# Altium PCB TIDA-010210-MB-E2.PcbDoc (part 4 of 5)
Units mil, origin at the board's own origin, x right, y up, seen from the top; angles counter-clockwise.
Board outline 11811.02 x 8661.42 mil, 4 copper layers (Top Layer, Gnd Layer, Pwr Layer, Bottom Layer), stack 94.4 mil thick; 473 components, 257 nets, 1291 pads, 289 vias.
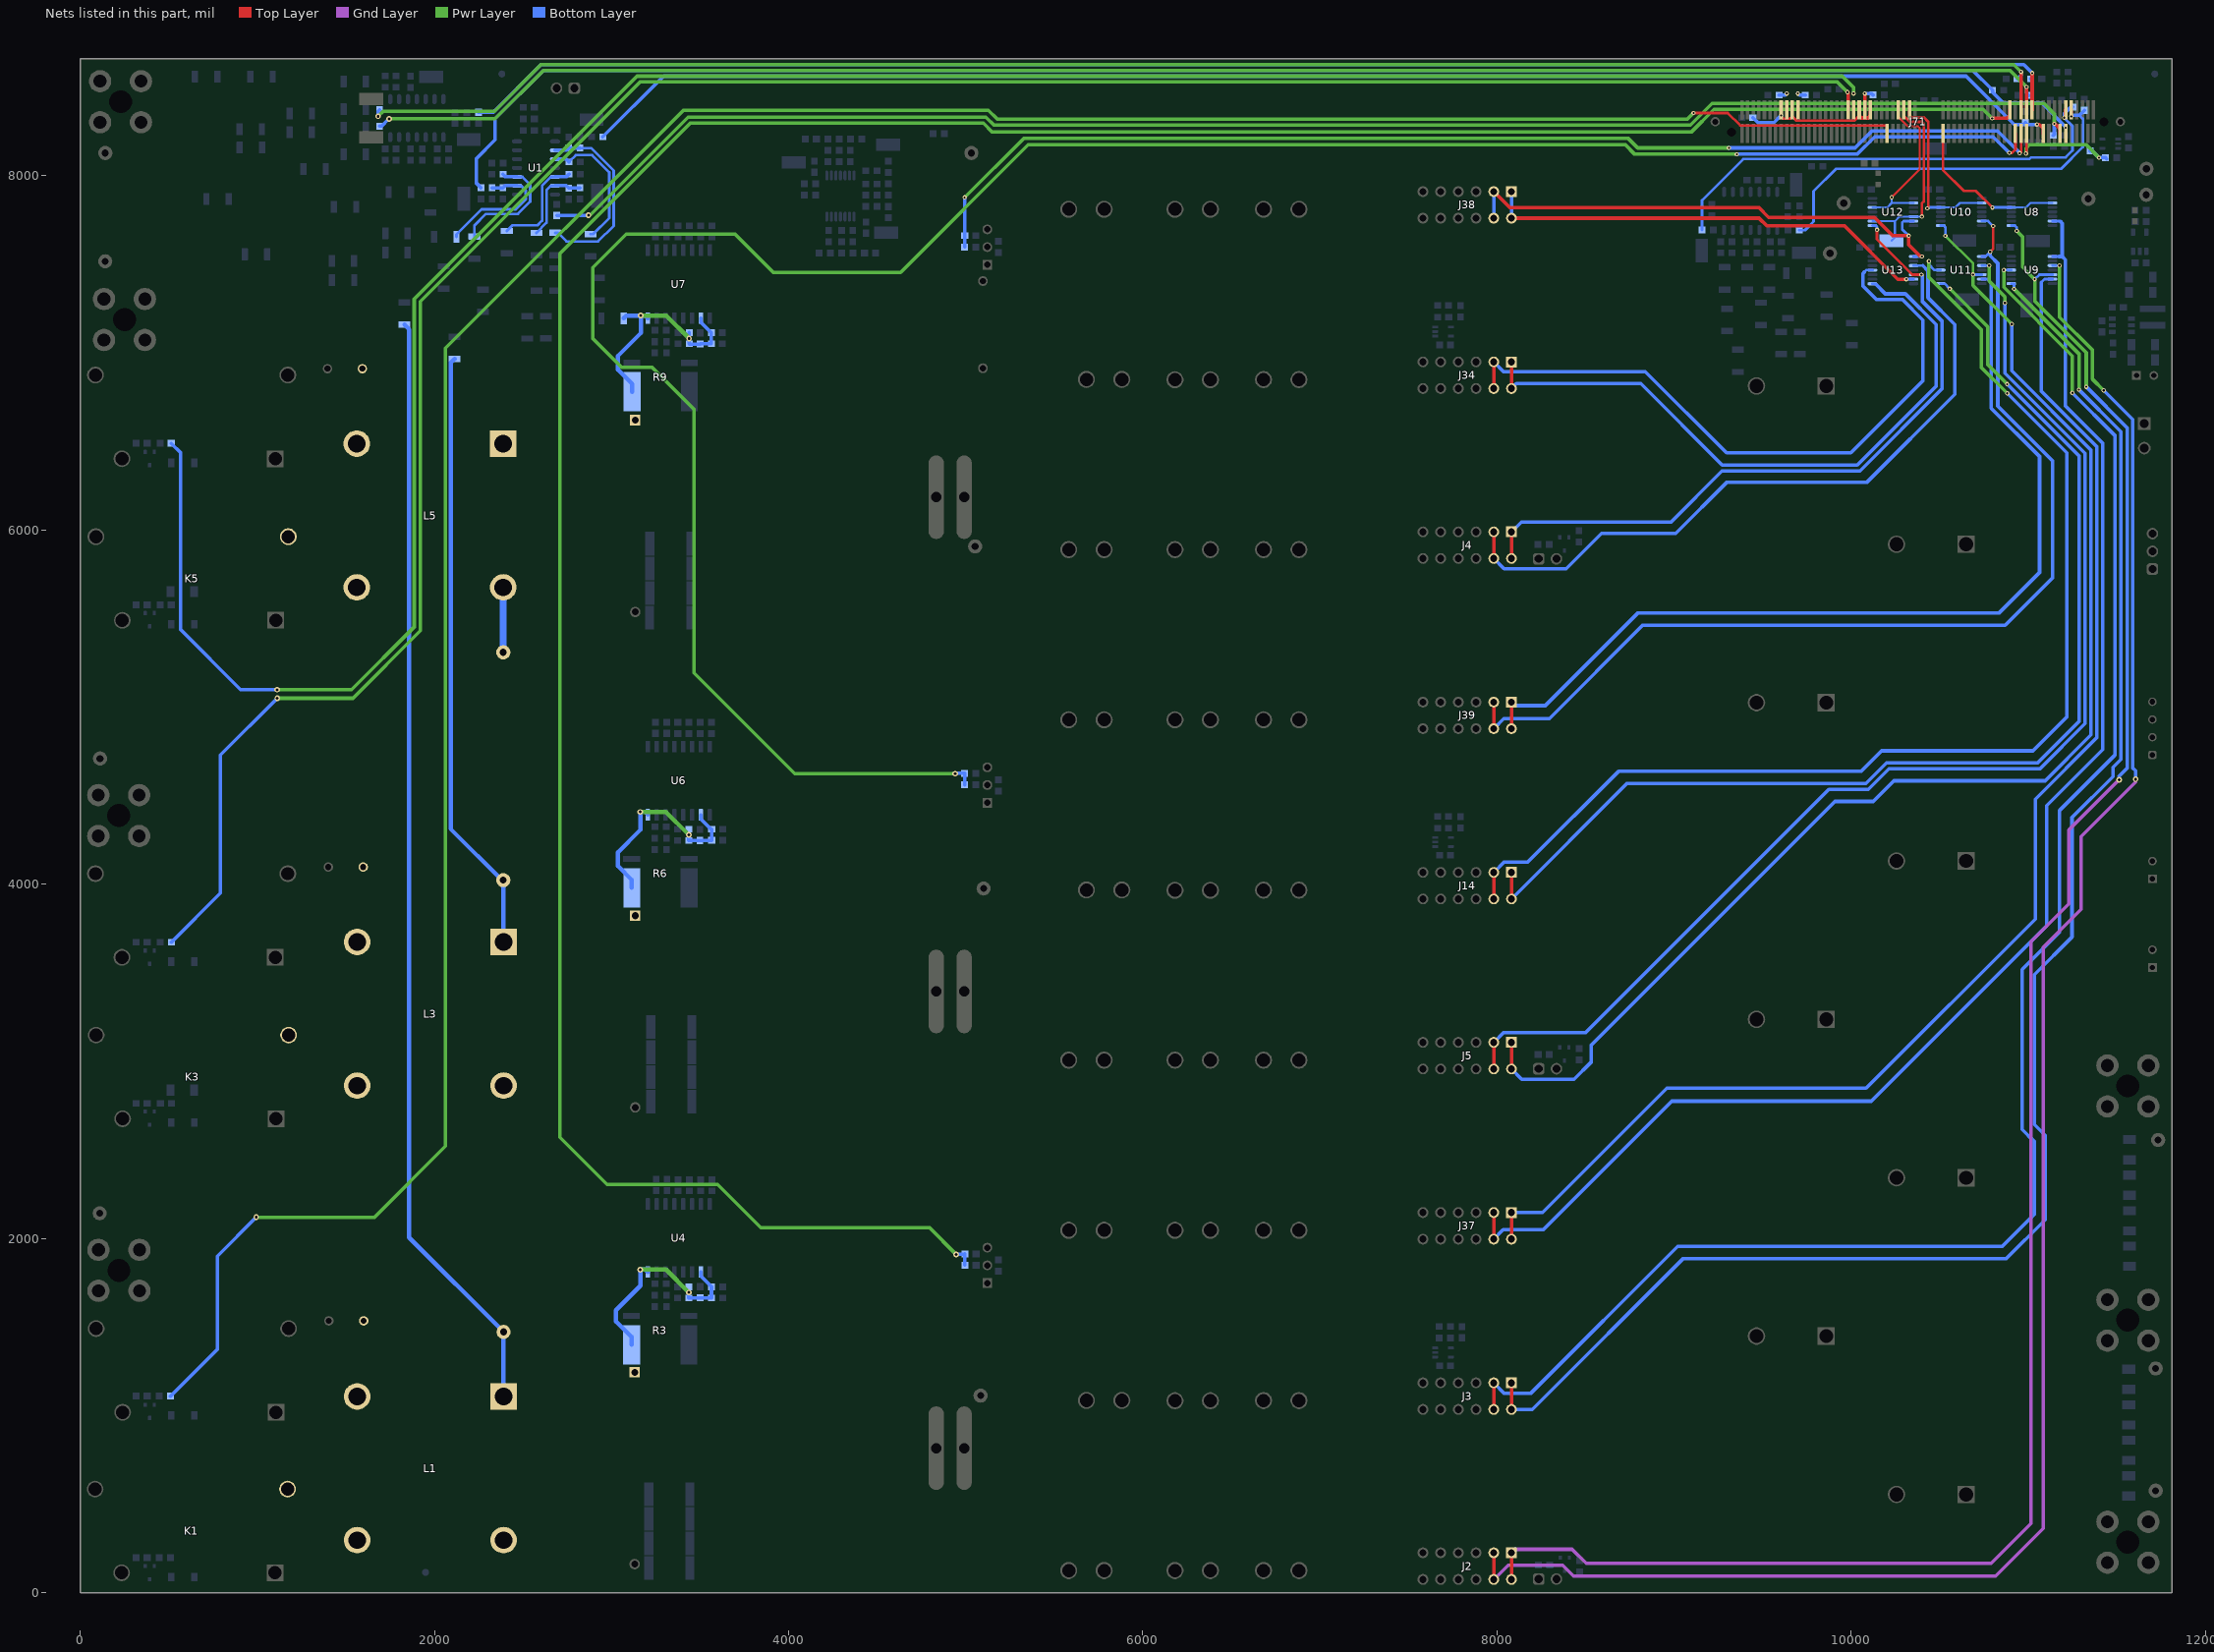
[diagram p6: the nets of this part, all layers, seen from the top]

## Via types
v1: diameter 24, hole 12, Top Layer to Bottom Layer, tented both sides, 169 vias
v2: diameter 32, hole 16, Top Layer to Bottom Layer, tented both sides, 102 vias
v3: diameter 50, hole 28, Top Layer to Bottom Layer, tented both sides, 18 vias

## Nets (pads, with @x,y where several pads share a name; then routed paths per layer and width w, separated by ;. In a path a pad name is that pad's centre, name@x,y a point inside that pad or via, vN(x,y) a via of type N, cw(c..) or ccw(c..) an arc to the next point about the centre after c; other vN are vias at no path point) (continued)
PWM+_C: J71.61 TP34.1 U12.5 U12.9 | length 1103.5
  Top Layer w15: J71.61@10296.51,8371.93 10296.51,8336.44 10329.71,8303.23 10399.82,8303.23 10409,8294.05 10409,7854.61 10398,7843.61 v1(10398,7769.19)
  Bottom Layer w12: U12.9@10119.04,7743.6 10119.04,7742.64 10245.4,7742.64 ; TP34.1@10227,7632.66 10245.4,7651.07 10245.4,7742.64 ; v1(10398,7769.19) U12.5@10351.33,7769.19 10271.96,7769.19 10245.4,7742.64
PWM-_A: J71.56 U8.2 U8.12 | length 923.3
  Top Layer w15: J71.56@10516.98,8238.07 10516.98,8031.52 10634.32,7914.18 10702.64,7914.18 v1(10796.45,7820.37)
  Bottom Layer w12: U8.12@10903.21,7820.77 10986.58,7820.77 11012.17,7846.36 U8.2@11135.49,7846.36
  Bottom Layer w15: v1(10796.45,7820.37) 10796.84,7820.77 U8.12@10903.21,7820.77
PWM-_B: J71.59 U10.2 U10.12 | length 963.4
  Top Layer w15: J71.59@10328,8371.93 10328,8342.11 10341.11,8329 10410.32,8329 10434,8305.32 10434,7820.37 v1(10429,7815.37)
  Bottom Layer w12: U10.12@10504.18,7820.77 10587.55,7820.77 10613.14,7846.36 U10.2@10736.46,7846.36
  Bottom Layer w15: v1(10429,7815.37) 10434.39,7820.77 U10.12@10504.18,7820.77
PWM-_C: J71.63 U12.2 U12.12 | length 919.2
  Top Layer w12: v1(10228,7877.78) 10386,8035.78 10386,8270 10376.86,8279.14 10317.5,8279.14 10265.01,8331.63 J71.63@10265.01,8371.93
  Bottom Layer w12: U12.12@10119.04,7820.37 10202.41,7820.37 10228,7845.97 ; v1(10228,7877.78) 10228,7845.97 ; U12.2@10351.33,7845.97 10228,7845.97
PWM_S1A: J2.1 U8.8 U9.5 | length 11142.9
  Top Layer w20: J2.1@8081.32,75.11 J2.1@8081.32,225.11
  Gnd Layer w20: J2.1@8081.32,225.11 8101.32,245.11 8423.89,245.11 8503,166 10788.68,166 11014,391.32 11014,3674.51 11228,3888.51 11228,4306 v2(11512,4590)
  Pwr Layer w20: v1(10933.49,7687.54) 10966.35,7654.68 10966.35,7484.18 v1(11035.35,7415.18) 11035.35,7292.65 11326.25,7001.75 v1(11326.25,6808.07)
  Bottom Layer w15: U8.8@10903.21,7718.41 10923.59,7718.41 10933.49,7708.51 v1(10933.49,7687.54) ; v1(11035.35,7415.18) 11061.68,7441.51 U9.5@11135.49,7441.51
  Bottom Layer w20: v1(11326.25,6808.07) 11557,6577.32 11557,4655 11512,4610
PWM_S1B: J5.1 U10.8 U11.5 | length 7593.4
  Top Layer w20: J5.1@8081.32,2957 J5.1@8081.32,3107
  Pwr Layer w15: v1(10531,7660.56) 10686.99,7504.57 v1(10686.99,7441.74)
  Pwr Layer w20: v1(10686.99,7441.74) 10686.99,7380.46 10905.46,7162 v1(10906,7162)
  Bottom Layer w15: U10.8@10504.18,7718.41 10520.59,7718.41 10531.43,7707.57 10531.43,7660.99 v1(10531,7660.56) ; v1(10686.99,7441.74) 10687.22,7441.51 U11.5@10736.46,7441.51
  Bottom Layer w20: J5.1@8081.32,2957 8139.32,2899 8435,2899 8530.5,2994.5 8530.5,3089.5 9908,4467 10123,4467 10240,4584 11094,4584 11353,4843 11353,6451 10906,6898 v1(10906,7162)
PWM_S1C: J4.1 U12.8 U13.5 | length 4085.3
  Top Layer w15: v1(10145,7694.39) 10145,7641.04 10345.08,7440.96 v1(10395.82,7440.96)
  Top Layer w20: J4.1@8081.32,5838.89 J4.1@8081.32,5988.89
  Bottom Layer w15: U12.8@10119.04,7718.01 10136.99,7718.01 10145,7710 v1(10145,7694.39) ; U13.5@10350.97,7440.76 U13.5@10351.33,7441.12 v1@10395.67,7441.12
  Bottom Layer w20: J4.1@8081.32,5988.89 8137.32,6044.89 8981.89,6044.89 9270,6333 10048,6333 10513.03,6798.03 10513.03,7178 10400.19,7290.84 10400.19,7436.6 v1(10395.82,7440.96) v1@10395.67,7441.12
PWM_S2A: J2.2 U9.3 | length 10986.7
  Top Layer w20: J2.2@7981.32,75.11 J2.2@7981.32,225.11
  Gnd Layer w20: J2.2@7981.32,75.11 8061.94,155.73 8370.27,155.73 8432,94 10814.5,94 11083,362.5 11083,3645 11297,3859 11297,4269 11605,4577 v2(11605,4593)
  Pwr Layer w20: v1(11175.14,7492.69) 11175.14,7201.56 11362,7014.7 11362,6850.5 v1(11424.5,6788)
  Bottom Layer w15: U9.3@11135.98,7493.18 U9.3@11135.49,7492.69 v1(11175.14,7492.69)
  Bottom Layer w20: v1(11424.5,6788) 11589,6623.5 11589,4656 11605,4640 v2(11605,4593)
PWM_S2B: J5.2 U11.3 | length 7086.1
  Top Layer w20: J5.2@7981.32,2957 J5.2@7981.32,3107
  Pwr Layer w20: v1(10778,7492.56) 10778,7404.78 10867,7315.78 v1(10867,7281.46)
  Bottom Layer w15: U11.3@10736.46,7492.69 10777.87,7492.69 v1(10778,7492.56)
  Bottom Layer w20: J5.2@7981.32,3107 8037.32,3163 8501,3163 9873,4535 10096,4535 10213,4652 11065.35,4652 11320,4906.65 11320,6432.37 10867,6885.37 v1(10867,7281.46)
PWM_S2C: J4.2 U13.3 | length 4039.2
  Top Layer w20: J4.2@7981.32,5838.89 J4.2@7981.32,5988.89
  Bottom Layer w15: U13.3@10351.33,7492.3 10403.19,7492.3
  Bottom Layer w20: J4.2@7981.32,5838.89 8039.32,5780.89 8389.89,5780.89 8589,5980 9008,5980 9298,6270 10089,6270 10585,6766 10585,7159 10432.82,7311.18 10432.82,7462.26 10403.19,7491.9 10403.19,7492.3
PWM_S3A: J37.1 U9.6 | length 7732.3
  Top Layer w20: J37.1@8081.32,1996.37 J37.1@8081.32,2146.37
  Bottom Layer w15: 11071.35,7396.6 11090.66,7415.92 U9.6@11135.49,7415.92
  Bottom Layer w20: J37.1@8081.32,2146.37 8256.97,2146.37 8958.6,2848 10083,2848 11038.3,3803.3 11038.3,4480.3 11385,4827 11385,6471.05 11071.35,6784.7 11071.35,7396.6
PWM_S3B: J39.1 U11.6 | length 5260.1
  Top Layer w20: J39.1@8081.32,4878.26 J39.1@8081.32,5028.26
  Bottom Layer w15: U11.6@10736.46,7415.92 10766.87,7415.92 10789.82,7392.96
  Bottom Layer w20: J39.1@8081.32,5028.26 8101.58,5008 8272,5008 8796,5532 10835,5532 11062.48,5759.48 11062.48,6414.36 10789.86,6686.98 10789.86,7392.92 10789.82,7392.96
PWM_S3C: J38.1 U13.6 | length 2562.8
  Top Layer w20: J38.1@8081.32,7760.15 9479.02,7760.15 9521.15,7718.01 9959.93,7718.01 10262.41,7415.52 v1(10310.17,7415.52)
  Bottom Layer w15: v1(10310.17,7415.52) U13.6@10351.33,7415.52
  Bottom Layer w20: J38.1@8081.32,7760.15 J38.1@8081.32,7910.15
PWM_S4A: J37.2 U8.6 U9.1 | length 8311.7
  Top Layer w20: J37.2@7981.32,1996.37 J37.2@7981.32,2146.37
  Bottom Layer w15: U9.1@11135.49,7545.01 11136.84,7543.66 11173,7543.66 ; U8.6@11135.49,7744 11136.49,7743 11178.9,7743
  Bottom Layer w20: J37.2@7981.32,1996.37 8033.95,2049 8261,2049 8987,2775 10113,2775 11103,3765 11103,4444 11419,4760 11419,6490 11208.72,6700.28 11208.72,7525.09 11190.15,7543.66 ; 11173,7543.66 11190.15,7543.66 ; 11178.9,7743 11190.15,7731.75 11190.15,7543.66
PWM_S4B: J39.2 U10.6 U11.1 | length 5930.3
  Top Layer w15: v1(10784.23,7570.36) 10800.24,7586.38 v1(10800.24,7715.54)
  Top Layer w20: J39.2@7981.32,4878.26 J39.2@7981.32,5028.26
  Bottom Layer w15: U11.1@10736.46,7543.87 10757.74,7543.87 v1(10784.23,7570.36) ; U10.6@10736.46,7744 10771.79,7744 v1(10800.24,7715.54)
  Bottom Layer w20: J39.2@7981.32,4878.26 8038.06,4935 8295,4935 8821,5461 10868,5461 11136,5729 11136,6390 10827,6699 10827,7504.98 10784.23,7547.76 v1(10784.23,7570.36)
PWM_S4C: J38.2 U12.6 U13.1 | length 2956.4
  Top Layer w15: v1(10398.39,7543.48) v1@10400.19,7545.27
  Top Layer w20: J38.2@7981.32,7910.15 8072.47,7819 9478.48,7819 9533.48,7764 10130.19,7764 10233.4,7660.78 v1(10324.19,7660.78) 10324.19,7610.08 10389,7545.27 v1@10400.19,7545.27
  Bottom Layer w15: v1(10324.19,7660.78) 10287.19,7697.78 10287.19,7734.78 10296,7743.6 U12.6@10351.33,7743.6 ; U13.1@10351.33,7543.48 v1(10398.39,7543.48)
  Bottom Layer w20: J38.2@7981.32,7760.15 J38.2@7981.32,7910.15
PWM_S5A: J3.1 U9.8 | length 9383.5
  Top Layer w20: J3.1@8081.32,1034.74 J3.1@8081.32,1184.74
  Pwr Layer w20: v1(10918.38,7361.06) 11285.04,6994.39 v1(11285.04,6791.54)
  Bottom Layer w15: U9.8@10903.21,7390.33 10918.38,7390.33 v1(10918.38,7361.06)
  Bottom Layer w20: J3.1@8081.32,1034.74 8198.74,1034.74 9051,1887 10876,1887 11094,2105 11094,2583 11034,2643 11034,3490 11246,3702 11246,4377 11477,4608 11477,4660 11522,4705 11522,6554.58 v1(11285.04,6791.54)
PWM_S5B: J14.1 U11.8 | length 6580.5
  Top Layer w20: J14.1@8081.32,3916.63 J14.1@8081.32,4066.63
  Pwr Layer w20: v1@10556.82,7362.18 v1(10555.82,7361.18) 10771,7146 10771,6932 v1(10880,6823)
  Bottom Layer w15: U11.8@10504.18,7390.33 10526.67,7390.33 v1(10555.82,7361.18)
  Bottom Layer w20: J14.1@8081.32,3916.63 8732.69,4568 10082,4568 10199,4685 11052,4685 11287,4920 11287,6416 v1(10880,6823)
PWM_S5C: J34.1 U13.8 | length 3751.3
  Top Layer w20: J34.1@8081.32,6798.52 J34.1@8081.32,6948.52
  Pwr Layer w20: J34.1@8081.32,6948.52 J34.1@8096.48,6948.52
  Bottom Layer w15: U13.8@10119.04,7389.93 10134.67,7389.93 U13.8@10139.5,7385.11
  Bottom Layer w20: J34.1@8081.32,6798.52 8108.8,6826 8811,6826 9271,6366 10033,6366 10478,6811 10478,7160 10305,7333 10191.61,7333 U13.8@10139.5,7385.11
PWM_S6A: J3.2 U9.11 | length 9522.2
  Top Layer w20: J3.2@7981.32,1034.74 J3.2@7981.32,1184.74
  Pwr Layer w20: v1(10861,7467) 10861,7369.47 11247.95,6982.52 v1(11247.95,6774)
  Bottom Layer w15: v1(10861,7467) 10861.1,7467.1 U9.11@10903.21,7467.1
  Bottom Layer w20: J3.2@7981.32,1184.74 8041.06,1125 8189,1125 9020,1956 10852.35,1956 11032,2135.65 11032,2547.72 10964,2615.72 10964,3518 11176,3730 11176,4417 11487.5,4728.5 11487.5,6534.45 v1(11247.95,6774)
PWM_S6B: J14.2 U11.11 | length 6741.4
  Top Layer w20: J14.2@7981.32,3916.63 J14.2@7981.32,4066.63
  Pwr Layer w20: v1(10438,7517) 10438,7426 10733,7131 10733,6918.43 v1(10880.43,6771)
  Bottom Layer w15: v1(10438,7517) 10438,7498 10468.9,7467.1 U11.11@10504.18,7467.1
  Bottom Layer w20: J14.2@7981.32,4066.63 8040.32,4125.63 8174.37,4125.63 8685.74,4637 10055,4637 10171,4753 11025,4753 11216,4944 11216,6435.51 10880.51,6771 v1(10880.43,6771)
PWM_S6C: J34.2 U13.11 | length 3846.6
  Top Layer w20: J34.2@7981.32,6798.52 J34.2@7981.32,6948.52
  Bottom Layer w15: 10072.19,7454.78 10084.11,7466.71 U13.11@10119.04,7466.71
  Bottom Layer w20: J34.2@7981.32,6948.52 8035.84,6894 8837,6894 9296,6435 9997,6435 10404,6842 10404,7184.61 10286.61,7302 10141,7302 10065.82,7377.18 10065.82,7448.42 10072.19,7454.78
RY_A: J71.68 R24.1 | length 15749
  Top Layer w15: v1(9109,8354) 9302,8354 9372.73,8283.27 10192.58,8283.27 10202.02,8273.84 J71.68@10202.02,8238.07
  Pwr Layer w20: v2(994,2120) 1662,2120 2062.76,2520.76 2062.76,7025.76 3406,8369 5127.91,8369 5176.91,8320 9075,8320 v1(9109,8354)
  Bottom Layer w20: R24.1@510.5,1110 774.54,1374.04 774.54,1900.54 v2(994,2120)
RY_B: J71.81 R25.1 | length 13144.8
  Top Layer w20: v1(9978,8472) 9981.55,8468.45 J71.81@9981.55,8371.93
  Pwr Layer w20: v2(1113,5050) 1541,5050 1921.5,5430.5 1921.35,5430.65 1921.35,7289.35 3161,8529 9921,8529 v1(9978,8472)
  Bottom Layer w20: R25.1@515.5,3673 792,3949.5 792,4729 v2(1113,5050)
RY_C: J71.79 R26.1 | length 13240.1
  Pwr Layer w20: v2(1112,5098) 1532,5098 1886,5452 1886,7304 3143.61,8561.61 9949.43,8561.61 10013.04,8498 v1(10013.04,8464)
  Bottom Layer w20: R26.1@514.5,6489 568,6435.5 568,5436 906,5098 v2(1112,5098)
SDFM_A: J71.75 R105.2 | length 141.6
  Top Layer w20: J71.75@10076.03,8371.93 v1(10076,8464)
  Bottom Layer w20: v1(10076,8464) 10114.22,8464 R105.2@10122.22,8456
SDFM_B: J71.99 R106.2 | length 44.9
  Bottom Layer w20: v1(9698.08,8464.02) 9706.53,8455.57 R106.2@9739.5,8455.57
SDFM_C: J71.103 R109.2 | length 46
  Bottom Layer w20: R109.2@9592.5,8455.57 9626.57,8455.57 v1(9635,8464)
SDFM_CLK: J71.73 J71.77 J71.101 J71.105 R110.2 | length 846.2
  Top Layer w15: v1(9603.59,8339.85) 9603.59,8333.41 9615.31,8321.69 9653.88,8321.69 J71.101@9666.58,8334.39 ; J71.101@9666.58,8371.93 J71.101@9666.58,8334.39 ; J71.77@10044.54,8338.54 10016,8310 9690.98,8310 J71.101@9666.58,8334.39
  Top Layer w20: J71.77@10044.54,8371.93 10044.54,8338.54 10057.08,8326 10096,8326 10107.53,8337.53 J71.73@10107.53,8371.93
  Bottom Layer w20: R110.2@9444,8328 9472.91,8299.09 9562.83,8299.09 v1(9603.59,8339.85)
Temp_A: C98.2 J71.31 R148.2 | length 16242.7
  Top Layer w20: v1(10795,8323.66) 10876.97,8323.66 10894.93,8341.62 J71.31@10894.93,8371.93
  Pwr Layer w20: v2(4946,1910) 4796,2060 3844,2060 3599.48,2304.52 2975.48,2304.52 2709,2571 2709,7560 3445,8296 5100,8296 5150,8246 9096.36,8246 9225.36,8375 10743.66,8375 v1(10795,8323.66)
  Bottom Layer w20: v2@4949,1913 v2(4946,1910) 4992.5,1910 C98.2@4995.5,1913 R148.2@4995.5,1849
TEMP_AMB: C101.2 J71.26 R156.2 | length 699.7
  Top Layer w15: v1@10989.42,8128.8 J71.26@10989.42,8238.07
  Pwr Layer w20: v1(10985.62,8125) 10985.62,8154.15 11005.47,8174 11325.75,8174 v1(11398,8101.75)
  Bottom Layer w20: C101.2@11348.68,8139.5 11360.26,8139.5 v1(11398,8101.75) R156.2@11434.24,8101.75 R156.2@11441,8094.99
TEMP_B: C94.2 J71.30 R146.2 | length 13151.3
  Top Layer w15: v1(10892,8128.77) 10907.77,8128.77 10926.43,8147.43 J71.30@10926.43,8238.07
  Pwr Layer w20: v2(4941,4624) 4034,4624 3466,5192 3466,6681 3228,6919 3056,6919 2895,7080 2895,7482 3082.99,7669.99 3698,7669.99 3913.99,7454 4631.95,7454 5351.95,8174 8724,8174 8777,8121 v1(9353,8121)
  Bottom Layer w20: v2(4941,4624) 4943,4626 C94.2@4993.5,4626 ; R146.2@4994,4560.06 4994,4623.61 C94.2@4994.5,4624.11 ; v1(9353,8121) 10032.27,8121 10131.27,8220 10800.77,8220 v1(10892,8128.77)
Temp_C: C85.2 J71.28 R142.2 | length 6603.8
  Top Layer w15: v1(10950,8127) 10957.92,8134.92 J71.28@10957.92,8238.07
  Pwr Layer w20: v1(4994,7877.29) 5326.61,8209.9 8741.1,8209.9 8794,8157 v1(9309,8157)
  Bottom Layer w20: v1(4994,7877.29) 4994.55,7876.74 C85.2@4994.55,7661.11 4994.05,7660.61 R142.2@4994.05,7597.06 ; v1(9309,8157) 10021,8157 10117,8253 10826,8253 10950,8129 v1(10950,8127)
VA_N: C14.2 R33.1 R38.2 U1.2 | length 743.9
  Bottom Layer w15: R38.2@2124.99,7655 2124.99,7667.99 2267,7810 2460,7810 2516,7866 2516,7917 2489.47,7943.53 U1.2@2466.55,7943.53
  Bottom Layer w20: C14.2@2325.29,7931.02 R33.1@2387.29,7931.02 2399.79,7943.53 U1.2@2466.55,7943.53
VA_P: R50.2 R57.2 U1.3 | length 706.3
  Bottom Layer w15: R50.2@2226,7656.99 2226,7718 2292,7784 2471.22,7784 2541,7853.78 2541,7949.83 2497.31,7993.53 U1.3@2466.55,7993.53
  Bottom Layer w20: R57.2@2387.33,8008.53 2402.33,7993.53 U1.3@2466.55,7993.53
VB_N: C20.2 R60.1 R65.2 U1.13 | length 470.7
  Bottom Layer w15: R65.2@2575.76,7676.99 2633,7734.23 2633,7918 2658.53,7943.53 U1.13@2681.12,7943.53
  Bottom Layer w20: U1.13@2681.12,7943.53 2745.41,7943.53 R60.1@2758.92,7930.02 2821.38,7930.02 C20.2@2822.38,7931.02
VB_P: R77.2 R84.2 U1.12 | length 599.5
  Bottom Layer w15: R77.2@2409,7687.99 2441.01,7720 2582,7720 2608,7746 2608,7943 2658.53,7993.53 U1.12@2681.12,7993.53
  Bottom Layer w20: U1.12@2681.12,7993.53 2745.4,7993.53 R84.2@2760.34,8008.46
VC_N: C26.2 R88.1 R91.2 U1.9 | length 1086.8
  Bottom Layer w15: R91.2@2682,7677.24 2697.76,7677.24 2746,7629 2924.5,7629 3012,7716.5 3012,8028 2883.97,8156.03 C26.2@2822.38,8156.03
  Bottom Layer w20: U1.9@2681.12,8143.53 2746.22,8143.53 R88.1@2758.38,8155.68 2822.02,8155.68 C26.2@2822.38,8156.03
VC_P: R99.2 R103.2 U1.10 | length 769.4
  Bottom Layer w15: R103.2@2760.22,8078.05 2798.11,8115.94 2890.06,8115.94 2987,8019 2987,7760 2896.99,7669.99 R99.2@2882,7669.99
  Bottom Layer w20: U1.10@2681.12,8093.53 2744.75,8093.53 R103.2@2760.22,8078.05
Vdc+_S: C19.1 J71.9 R47.2 | length 2208.3
  Top Layer w20: v1(11241.39,8335.17) J71.9@11241.39,8371.93
  Bottom Layer w15: R47.2@9706.5,7692 9738,7692 9787,7741 9787,7912 9914,8039 11184.78,8039 11307.83,8162.05 11307.83,8319.93 11287.24,8340.51
  Bottom Layer w20: v1(11241.39,8335.17) 11246.73,8340.51 11287.24,8340.51 C19.1@11315.73,8369
Vdc-_S: C25.1 J71.11 R74.2 | length 2715.1
  Top Layer w20: v1(11201.95,8327) 11209.89,8334.95 J71.11@11209.89,8371.93
  Bottom Layer w15: R74.2@9157.29,7693.99 9157.29,7860.83 9389.98,8093.53 11005.41,8093.53 11015.11,8103.23 11209.82,8103.23 11248.59,8142 11248.59,8280.36 v1(11201.95,8327)
  Bottom Layer w20: v1(11201.95,8327) 11201.95,8350.86 11238.59,8387.5 C25.1@11250.84,8387.5
VG_SEN_A: C18.1 J71.23 R46.2 | length 9147.4
  Top Layer w20: J71.23@11020.92,8371.93 11020.92,8578.92 v1(11021,8579)
  Bottom Layer w20: R46.2@2249,8357.99 2332.99,8357.99 2602,8627 10973.5,8627 11021,8579.5 v1(11021,8579) 11021,8554.89 C18.1@11012.11,8546
VG_SEN_B: C24.1 J71.25 R73.2 | length 9651.4
  Top Layer w20: J71.25@10989,8372.35 J71.25@10989.42,8371.93 10989.42,8500.58 v1(10989,8501)
  Pwr Layer w20: v2(1744,8321) 2343.19,8321 2616.19,8594 10896,8594 v1(10989,8501)
  Bottom Layer w20: R73.2@1690,8279.14 1702.14,8279.14 v2(1744,8321) ; v1(10989,8501) 10989,8466.66 C24.1@11002.66,8453
VG_SEN_C: C29.1 J71.27 R96.2 | length 9716.6
  Top Layer w20: J71.27@10957.92,8371.93 10957.92,8585.92 v1(10958,8586)
  Pwr Layer w20: v2(1682,8335.08) 1710.92,8364 2339,8364 2602,8627 10917,8627 v1(10958,8586)
  Bottom Layer w20: v2(1682,8335.08) 1682,8363.5 R96.2@1690,8371.5 ; C29.1@10936.5,8546 10958,8567.5 v1(10958,8586)
VINV_A: K1.4 L1.2 L1.3 RT1.2
VINV_B: K3.4 L3.2 L3.3 RT2.2
VINV_C: K5.4 L5.2 L5.3 RT3.2
VINV_SEN_A: C17.1 J71.12 R45.2 | length 9566.7
  Bottom Layer w20: R45.2@2263,7931.5 2238,7956.5 2238,8097 2343.19,8202.19 2343.19,8321 2616.19,8594 10685.84,8594 C17.1@10797,8482.84 10797,8470 10857,8410 11074.48,8410 11210,8274.48 v1(11210,8271)
VINV_SEN_B: C23.1 J71.14 R72.2 | length 8972
  Top Layer w20: v1(11146.06,8293) 11150.71,8293 11178.4,8265.32 J71.14@11178.4,8238.07
  Pwr Layer w20: v2(2870,7776) 2878,7776 3432,8330 5114,8330 5159,8285 9091,8285 9213,8407 11087.23,8407 11146.06,8348.17 v1(11146.06,8293)
  Bottom Layer w20: R72.2@2691,7775.5 2869.5,7775.5 v2(2870,7776) ; C23.1@11140.13,8228 11146.06,8233.93 v1(11146.06,8293)
VINV_SEN_C: C28.1 J71.20 R95.2 | length 8436.9
  Top Layer w20: v1(11048,8289) 11061.52,8289 11083.91,8266.61 J71.20@11083.91,8238.07
  Bottom Layer w20: R95.2@2950.7,8219.02 3293.29,8561.61 10647.39,8561.61 10920,8289 C28.1@10982.47,8289 ; C28.1@10982,8299.89 10982,8289.47 C28.1@10982.47,8289 ; v1(11048,8289) C28.1@10982.47,8289
Vsen_A: C10.1 C41.1 C44.2 C46.1 C47.2 C48.2 L1.1 L1.4 R3.2 R48.1 TP2.1 U4.2 U4.8 | length 7508.4
  Pwr Layer w25: v2(3162.94,1824.13) 3307.26,1824.13 v2(3436.43,1694.96)
  Bottom Layer w20: v2(3436.43,1694.96) C46.1@3436.43,1663.46 3498.46,1663.46 C47.2@3500,1665 3562.9,1665 C44.2@3564.44,1663.46 C41.1@3564.44,1726.46 3564.44,1728.56 3504.94,1788.06 U4.2@3504.94,1811
  Bottom Layer w25: R48.1@1831,7159.01 1857,7133.01 1857,2006 TP2.1@2390.77,1472.23 L1.1@2390.77,1108.02 ; R3.2@3112.99,1399.57 3112.99,1444.01 3025,1532 3025,1595 3162.94,1732.94 v2(3162.94,1824.13) 3191.81,1824.13 U4.8@3204.94,1811
Vsen_B: C11.1 C54.1 C57.2 C59.1 C60.2 C61.2 L3.1 L3.4 R6.2 R75.1 TP4.1 U6.2 U6.8 | length 4649.3
  Pwr Layer w25: v2(3162.5,4408.18) 3306.75,4408.18 v2(3436.43,4278.5)
  Bottom Layer w20: v2(3162.5,4408.18) 3188.75,4408.18 U6.8@3204.93,4392 ; v2(3436.43,4278.5) C59.1@3436.43,4247 3498.5,4247 C60.2@3499,4246.5 3564.56,4246.5 C57.2@3566.06,4248 C54.1@3566.06,4311 3561.16,4311 3504.93,4367.23 U6.2@3504.93,4392
  Bottom Layer w25: R75.1@2114,6965 2091.76,6942.76 2091.76,6898.75 2091.76,4312.24 2390.77,4013.23 L3.1@2390.77,3674.02 ; R6.2@3114.92,3979.57 3114.92,4023.72 3035.16,4103.49 3035.16,4179.16 3162.5,4306.5 v2(3162.5,4408.18)
Vsen_C: C9.1 C67.1 C70.2 C72.1 C75.2 C76.2 L5.1 L5.4 R9.2 R97.1 TP7.1 U7.2 U7.8 | length 1716.1
  Pwr Layer w25: v2(3165,7210.18) 3309.32,7210.18 v2(3438.5,7081)
  Bottom Layer w20: C76.2@3438.5,7114 v2(3438.5,7081) C72.1@3438.5,7051 3439.99,7049.5 C75.2@3500.93,7049.5 3502.43,7051 C70.2@3563.5,7051 C67.1@3563.5,7114 3505,7172.5 U7.2@3505,7196
  Bottom Layer w25: R97.1@3068.99,7195 3084.17,7210.18 v2(3165,7210.18) ; R9.2@3115.99,6780.57 3115.99,6825.01 3037,6904 3037,6983 3165,7111 v2(3165,7210.18) ; U7.8@3205,7196 3190.82,7210.18 v2(3165,7210.18)
  Bottom Layer w40: L5.4@2388.77,5676 2388.77,5309.23 TP7.1@2389,5309
pads on no net: FID1.1 FID2.1 FID3.1 J1. J2.5 J3.3 J3.5 J4.5 J5.5 J14.3 J14.5 J31. J34.3 J34.5 J37.5 J38.5 J39.5 J66. J67. J68. J69. J70. J71.1 J71.2 J71.3 J71.4 J71.5 J71.6 J71.8 J71.32 J71.33 J71.34 J71.36 J71.37 J71.39 J71.40 J71.41 J71.42 J71.43 J71.44 J71.45 J71.58 J71.60 J71.64 J71.66 J71.72 J71.78 J71.80 J71.82 J71.85 J71.86 J71.87 J71.88 J71.89 J71.90 J71.91 J71.92 J71.93 J71.94 J71.95 J71.96 J71.100 J71.102 J71.104 J71.106 J71.107 J71.108 J71.109 J71.110 J71.113 J71.114 J71.115 J71.116 J71.117 J71.118 J71.119 J71.120 J71.181 J71.182 J71.185 J71.186 LBL1.0 U4.4 U4.14 U6.4 U6.14 U7.4 U7.14 U16.4

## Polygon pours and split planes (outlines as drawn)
NEU on Top Layer "TOP_LAYER_NEU_P182" (solid, remove dead copper, pour order 182): 9871,1721 9807,1657 9807,1348 9838,1317 11742,1317 11754,1329 11754,1699 11732,1721
PH_C on Top Layer "TOP_LAYER_PH_C_P146" (solid, remove dead copper, pour order 146): 29.17,6847.67 54.83,6822 260,6822 461,7023 461,7401 273,7589 72,7589 29.17,7546.17
PH_B on Top Layer "TOP_LAYER_PH_B_P144" (solid, remove dead copper, pour order 144): 29.17,4032.67 54.83,4007 260,4007 461,4208 461,4586 273,4774 72,4774 29.17,4731.17
PH_A on Top Layer "TOP_LAYER_PH_A_P142" (solid, remove dead copper, pour order 142): 33.17,1464.67 58.83,1439 264,1439 465,1640 465,2018 277,2206 76,2206 33.17,2163.17
VINV_C on Top Layer "TOP_LAYER_VINV_C_P141" (solid, remove dead copper, pour order 141): 1489.45,6726.45 1564,6801 1564,6931 1584,6951 1624,6951 1649,6926 1649,5634 1607,5592 1530,5592 1486,5636 1486,5679 1256,5909 1149,5909 1119,5939 1119,5986 1149,6016 1295,6016 1489.45,6210.45
VINV_B on Top Layer "TOP_LAYER_VINV_B_P139" (solid, remove dead copper, pour order 139): 1491.14,3912.39 1565.69,3986.94 1565.69,4116.94 1585.69,4136.94 1625.69,4136.94 1650.69,4111.94 1650.69,2819.94 1608.69,2777.94 1531.69,2777.94 1487.69,2821.94 1487.69,2864.94 1257.69,3094.94 1150.69,3094.94 1120.69,3124.94 1120.69,3171.94 1150.69,3201.94 1296.69,3201.94 1491.14,3396.39
NetK5_3 on Top Layer "TOP_LAYER_NETK5_3_P137" (solid, remove dead copper, pour order 137): 400,6016 564.45,6180.45 564.45,6780.45 783,6999 1410,6999 1455,6954 1455,6874 1392,6811 954,6811 727.45,6584.45 727.45,6018.45 582,5873 55.45,5873 22,5906.45 22,5987 51,6016
NetK3_3 on Top Layer "TOP_LAYER_NETK3_3_P135" (solid, remove dead copper, pour order 135): 401.69,3201.94 566.14,3366.39 566.14,3966.39 784.69,4184.94 1411.69,4184.94 1456.69,4139.94 1456.69,4059.94 1393.69,3996.94 955.69,3996.94 729.14,3770.39 729.14,3204.39 583.69,3058.94 57.14,3058.94 23.69,3092.39 23.69,3172.94 52.69,3201.94
NetK1_3 on Top Layer "TOP_LAYER_NETK1_3_P133" (solid, remove dead copper, pour order 133): 396,639 560.45,803.45 560.45,1403.45 779,1622 1406,1622 1451,1577 1451,1497 1388,1434 950,1434 723.45,1207.45 723.45,641.45 578,496 51.45,496 18,529.45 18,610 47,639
VINV_A on Top Layer "TOP_LAYER_VINV_A_P128" (solid, remove dead copper, pour order 128): 1485.45,1349.45 1560,1424 1560,1554 1580,1574 1620,1574 1645,1549 1645,257 1603,215 1526,215 1482,259 1482,302 1252,532 1145,532 1115,562 1115,609 1145,639 1291,639 1485.45,833.45
NEU on Top Layer "TOP_LAYER_NEU_P068" (solid, remove dead copper, pour order 68): 3451,6263 2234,6263 2156,6341 2156,7139 727,8568 448,8568 386,8630 89,8630 30,8571 30,8266 86,8210 580,8210 1788,7002 1788,6115 2008,5895 3121,5895 3863.11,5152.89 5952,5152.89 6104,5000.89 6104,4895.89 6152,4847.89 6410,4847.89 6460,4897.89 6460,5035.75 6964,5539.75 6964,5922.89 6919,5967.89 6646,5967.89 6604,5925.89 6604,5752.89 6506,5654.89 4059.11,5654.89
DC- on Top Layer "TOP_LAYER_DC-_P064" (solid, remove dead copper, pour order 64): 9681,2530 9568,2417 9568,1378 9508,1318 9210,1318 9115,1413 9115,6771 9231,6887 9232,6886 9501.09,6886.09 9568,6819.18 9568,3156 9683,3041 11714,3041 11754,3001 11754,2591 11693,2530
NetJ7_1 on Top Layer "TOP_LAYER_NETJ7_1_P054" (solid, remove dead copper, pour order 54): 5812,2125.22 5861,2076.22 5861,1980.22 6049,1792.22 6447,1792.22 6960,1279.22 6960,1035.22 6925,1000.22 6647,1000.22 6603,1044.22 6603,1199.72 6416.5,1386.22 5964,1386.22 5501,1849.22 5501,2088.22 5538,2125.22
NetJ32_1 on Top Layer "TOP_LAYER_NETJ32_1_P052" (solid, remove dead copper, pour order 52): 5812,5007.11 5861,4958.11 5861,4862.11 6049,4674.11 6447,4674.11 6960,4161.11 6960,3917.11 6925,3882.11 6647,3882.11 6603,3926.11 6603,4081.61 6416.5,4268.11 5964,4268.11 5501,4731.11 5501,4970.11 5538,5007.11
NetJ25_1 on Top Layer "TOP_LAYER_NETJ25_1_P020" (solid, remove dead copper, pour order 20): 4930,590 4963.77,556.23 5470.01,556.23 5960,1046.22 5960,1123.22 5913,1170.22 5063.22,1170.22 4930,1037
NetJ40_1 on Top Layer "TOP_LAYER_NETJ40_1_P018" (solid, remove dead copper, pour order 18): 4930,3177 4970,3137.67 5169.56,3137.67 5960,3928.11 5960,4005.11 5913,4052.11 5094.11,4052.11 4930,3888
NetJ16_1 on Top Layer "TOP_LAYER_NETJ16_1_P016" (solid, remove dead copper, pour order 16): 6152,1170.22 6100,1118.22 6100,961.22 5491,352.22 5491,87.22 5547,31.22 5795,31.22 6459,695.22 6459,1121.22 6410,1170.22
NetJ23_1 on Top Layer "TOP_LAYER_NETJ23_1_P014" (solid, remove dead copper, pour order 14): 6152,4052.11 6100,4000.11 6100,3843.11 5491,3234.11 5491,2969.11 5547,2913.11 5795,2913.11 6459,3577.11 6459,4003.11 6410,4052.11
NetJ42_1 on Top Layer "TOP_LAYER_NETJ42_1_P004" (solid, remove dead copper, pour order 4): 5812,7889 5861,7840 5861,7744 6049,7556 6447,7556 6960,7043 6960,6799 6925,6764 6647,6764 6603,6808 6603,6963.5 6416.5,7150 5964,7150 5501,7613 5501,7852 5538,7889
NetJ26_1 on Top Layer "TOP_LAYER_NETJ26_1_P002" (solid, remove dead copper, pour order 2): 6152,6934 6100,6882 6100,6725 5491,6116 5491,5851 5547,5795 5795,5795 6459,6459 6459,6885 6410,6934
NetJ56_1 on Top Layer "TOP_LAYER_NETJ56_1_P000" (solid, remove dead copper, pour order 0): 4930,5980 4974,5936 5086,5936 5960,6810 5960,6887 5913,6934 5397,6934 4930,6467
GND on Bottom Layer "BOTTOM_LAYER_GND_P190" (solid, remove dead copper, pour order 190): 2542,8307 2549,8300 2626,8300 2634,8308 2634,8410 2630,8414 2548,8414 2542,8408
1.65V_C on Bottom Layer "BOTTOM_LAYER_1.65V_C_P188" (solid, remove dead copper, pour order 188): 4205,7799 4200,7794 4200,7679 4207,7672 4244,7672 4251,7679 4251,7797 4249,7799
NetJ42_1 on Bottom Layer "BOTTOM_LAYER_NETJ42_1_P180" (solid, remove dead copper, pour order 180): 5812,7889 5861,7840 5861,7744 6049,7556 6447,7556 6960,7043 6960,6799 6925,6764 6647,6764 6603,6808 6603,6963.5 6416.5,7150 5964,7150 5501,7613 5501,7852 5538,7889
NetJ26_1 on Bottom Layer "BOTTOM_LAYER_NETJ26_1_P178" (solid, remove dead copper, pour order 178): 6152,6934 6100,6882 6100,6725 5491,6116 5491,5851 5547,5795 5795,5795 6459,6459 6459,6885 6410,6934
NetJ56_1 on Bottom Layer "BOTTOM_LAYER_NETJ56_1_P176" (solid, remove dead copper, pour order 176): 4930,5980 4974,5936 5086,5936 5960,6810 5960,6887 5913,6934 5397,6934 4930,6467
NetJ32_1 on Bottom Layer "BOTTOM_LAYER_NETJ32_1_P174" (solid, remove dead copper, pour order 174): 5812,5007.11 5861,4958.11 5861,4862.11 6049,4674.11 6447,4674.11 6960,4161.11 6960,3917.11 6925,3882.11 6647,3882.11 6603,3926.11 6603,4081.61 6416.5,4268.11 5964,4268.11 5501,4731.11 5501,4970.11 5538,5007.11
NetJ23_1 on Bottom Layer "BOTTOM_LAYER_NETJ23_1_P172" (solid, remove dead copper, pour order 172): 6152,4052.11 6100,4000.11 6100,3843.11 5491,3234.11 5491,2969.11 5547,2913.11 5795,2913.11 6459,3577.11 6459,4003.11 6410,4052.11
NetJ40_1 on Bottom Layer "BOTTOM_LAYER_NETJ40_1_P170" (solid, remove dead copper, pour order 170): 4930,3177 4970,3137.67 5169.56,3137.67 5960,3928.11 5960,4005.11 5913,4052.11 5094.11,4052.11 4930,3888
NetJ7_1 on Bottom Layer "BOTTOM_LAYER_NETJ7_1_P168" (solid, remove dead copper, pour order 168): 5812,2125.22 5861,2076.22 5861,1980.22 6049,1792.22 6447,1792.22 6960,1279.22 6960,1035.22 6925,1000.22 6647,1000.22 6603,1044.22 6603,1199.72 6416.5,1386.22 5964,1386.22 5501,1849.22 5501,2088.22 5538,2125.22
NetJ16_1 on Bottom Layer "BOTTOM_LAYER_NETJ16_1_P166" (solid, remove dead copper, pour order 166): 6152,1170.22 6100,1118.22 6100,961.22 5491,352.22 5491,87.22 5547,31.22 5795,31.22 6459,695.22 6459,1121.22 6410,1170.22
NetJ25_1 on Bottom Layer "BOTTOM_LAYER_NETJ25_1_P164" (solid, remove dead copper, pour order 164): 4930,590 4963.77,556.23 5470.01,556.23 5960,1046.22 5960,1123.22 5913,1170.22 5063.22,1170.22 4930,1037
NEU on Bottom Layer "BOTTOM_LAYER_NEU_P162" (solid, remove dead copper, pour order 162): 3426,632 3410.8,616.8 3410.8,75.2 3466,20 3561,20 3604,63 3604,587 3559,632
GND on Bottom Layer "BOTTOM_LAYER_GND_P156" (solid, remove dead copper, pour order 156): 11520,7529.91 11505,7514.91 11505,7310.91 11512,7303.91 11565,7303.91 11571,7297.91 11571,7184.91 11576,7179.91 11603.79,7179.91 11609.79,7185.91 11609.79,7467.7 11624,7481.91 11624,7520.91 11615,7529.91
5V on Bottom Layer "BOTTOM_LAYER_5V_P154" (solid, remove dead copper, pour order 154): 11653,7540.91 11644,7531.91 11644,7311.91 11624,7291.91 11624,7229.91 11631,7222.91 11773.69,7222.91 11780.69,7229.91 11780.69,7426.22 11709,7497.91 11709,7592.91 11705,7596.91 11654.53,7596.91 11653,7595.39
GND on Bottom Layer "BOTTOM_LAYER_GND_P152" (solid, remove dead copper, pour order 152): 11780.69,7080.91 11786,7075.61 11786,6851.91 11781,6846.91 11686,6846.91 11683,6849.91 11683,7072.91 11691,7080.91
+12V on Bottom Layer "BOTTOM_LAYER_+12V_P148" (solid, remove dead copper, pour order 148): 11564,7131.91 11556,7123.91 11556,6851.99 11568.07,6839.91 11633.79,6839.91 11637.79,6843.91 11637.79,6901.13 11609.79,6929.13 11609.79,7124.13 11602,7131.91
Vsen_A on Bottom Layer "BOTTOM_LAYER_VSEN_A_P126" (solid, remove dead copper, pour order 126): 3192,1166 3192,1493 3161,1524 2387,1524 2313,1450 2313,263 2360,216 2434,216 2467,249 2467,441
Vsen_B on Bottom Layer "BOTTOM_LAYER_VSEN_B_P124" (solid, remove dead copper, pour order 124): 3192,3732 3192,4059 3161,4090 2404,4090 2313,3999 2313,2829 2360,2782 2434,2782 2467,2815 2467,3007
Vsen_C on Bottom Layer "BOTTOM_LAYER_VSEN_C_P122" (solid, remove dead copper, pour order 122): 3190,6545 3190,6872 3171,6891 2803,6891 2751,6839 2564,6839 2311,6586 2311,5642 2358,5595 2432,5595 2465,5628 2465,5820
NEU on Bottom Layer "BOTTOM_LAYER_NEU_P118" (solid, remove dead copper, pour order 118): 3417,5986 3417,5443 3426,5434 3947.89,5434 4229,5152.89 5952,5152.89 6104,5000.89 6104,4895.89 6152,4847.89 6410,4847.89 6460,4897.89 6460,5035.75 6964,5539.75 6964,5922.89 6919,5967.89 6646,5967.89 6604,5925.89 6604,5752.89 6506,5654.89 4527,5654.89 4174.89,6007 3438,6007
NetC10_2 on Bottom Layer "BOTTOM_LAYER_NETC10_2_P116" (solid, remove dead copper, pour order 116): 3233,629 3252,610 3252,86 3224,58 3126,58 3091,93 3091,576 3144,629
NetC11_2 on Bottom Layer "BOTTOM_LAYER_NETC11_2_P108" (solid, remove dead copper, pour order 108): 3247,3262 3233,3276 3171,3276 3084,3189 3084,2713.88 3098,2699.88 3241,2699.88 3247,2705.88
NetC9_2 on Bottom Layer "BOTTOM_LAYER_NETC9_2_P106" (solid, remove dead copper, pour order 106): 3248,5440 3242,5434 3099,5434 3085,5448 3085,5951 3140,6006 3225,6006 3248,5983
NEU on Bottom Layer "BOTTOM_LAYER_NEU_P066" (solid, remove dead copper, pour order 66): 3417,3249 3417,2711 3428,2700 3800,2700 4178,2322 5901,2322 6104,2119 6104,2014 6152,1966 6410,1966 6460,2016 6460,2153.86 6964,2657.86 6964,3041 6919,3086 6646,3086 6604,3044 6604,2885 6512,2793 4507,2793 4026,3274 3442,3274
NetL2_2 on Bottom Layer "BOTTOM_LAYER_NETL2_2_P040" (solid, remove dead copper, pour order 40): 4776,1510 4894,1392 4894,586 4854,546 4695,546 4174,1067 3420,1067 3353,1134 3353,1475 3388,1510
NetL4_2 on Bottom Layer "BOTTOM_LAYER_NETL4_2_P038" (solid, remove dead copper, pour order 38): 4778,4090 4896,3972 4896,3166 4856,3126 4697,3126 4176,3647 3422,3647 3355,3714 3355,4055 3390,4090
NetL6_2 on Bottom Layer "BOTTOM_LAYER_NETL6_2_P036" (solid, remove dead copper, pour order 36): 4779,6891 4897,6773 4897,5977 4860,5940 4685,5940 4177,6448 3423,6448 3356,6515 3356,6856 3391,6891
GND on Gnd Layer "GND_LAYER_GND_P186" (solid, remove dead copper, pour order 186): 2281,7550 2685,7146 2685,6190 2685,2289 2912.75,2061.25 3652.23,2061.25 4050.49,1663 5154,1663 5240,1749 5240,2017.23 5109.23,2148 4174,2148 3573.68,2748.32 3573.68,4013.32 3539.47,4047.52 3350.21,4047.52 3214.73,4183 3072.5,4183 2938.5,4317 2938.5,4520.14 3063.66,4645.3 3651.8,4645.3 3912.1,4385 3913,4385 5171,4385 5239,4453 5239,4679 5167,4751 4050,4751 3571,5230 3571,6812.07 3533.55,6849.52 3352.71,6849.52 3217.23,6985 3075,6985 2941,7119 2941,7353 3138,7550 3727,7550 3923,7354 5110,7354 5287,7531 5287,7950 5448,8111 7003,8111 7385,7729 8753,7729 9282.51,7199.49 10235.58,7199.49 11031,6404.06 11031,4821 11285,4567 11734,4567 11786,4619 11786,7100 11769,7117 11635,7117 11634,7116 11616,7134 11616,7267 11632,7283 11768,7283 11786,7301 11786,8582 11727,8641 1233,8641 1211,8619 1211,8398 2059,7550
NEU on Gnd Layer "GND_LAYER_NEU_P120" (solid, remove dead copper, pour order 120): 9244.9,6919.06 9290.94,6873.02 9290.94,6740.26 9391.94,6639.26 9593.26,6639.26 9823.01,6869.01 10149.02,6868.98 10344,6674 10344,531 10279,466 7479.59,466 7478.08,467.51 7041.79,31.22 6650,31.22 6552,129.22 6552,196 6450,298 5505,298 5227,20 3465,20 3410.8,74.2 3410.8,616.8 3426,632 4356,632 4536,452 5060,452 5186,578 5186,945.57 5270.34,1030.66 5270.34,1468.3 5673.68,1873.26 5853.68,1873.26 5955.68,1975.26 5955.68,2119.26 5854.68,2220.26 5455,2220.26 5342.74,2220.26 5015,2548 5015,2991 5182,3158 5182,3799 5276,3893 5276,4180.22 5458.5,4368.42 5458.5,4694 5458.5,4704.02 5509,4754.52 5853,4754.52 5955,4856.52 5955,5000.52 5854,5101.52 5162,5101.52 5007,5256.52 5007,5614 5225,5832 5225,6424 5015,6632.28 5015,6951.35 5225,7161.35 5696.7,7636 5852.59,7636 5955,7738.41 5955,7841 6001,7888 6459,7888 6508,7839 6508,7737.41 6609.91,7635.5 7167,7635.5 7283.5,7519 8645.06,7519
DC- on Pwr Layer "PWR_LAYER_DC-_P158" (solid, remove dead copper, pour order 158): 8298,4637.11 8741.89,5081 9497,5081 9570,5008 9570,3257.94 9494.06,3182 9426,3182 8298.89,4309.11 7023,4309.11 6601,4731.11 6601,4970.11 6638,5007.11 6914,5007.11 7284,4637.11
DC+ on Pwr Layer "PWR_LAYER_DC+_P094" (solid, remove dead copper, pour order 94): 10344,3041 10514,3211 10514,5123 10408,5229 9313,5229 8315,6227 6643.42,6227 6465,6048.58 6465,5843.78 6426,5804.78 6142,5804.78 6076,5870.78 6076,6326.78 6305.22,6556 8622,6556 9455,5723 10425,5723 10514,5812 10514,5935 10551,5972 10961,5972 11025,5908 11025,826 11350,501 11686,501 11753,434 11753,131 11686,64 10713.32,64 10514,263.32 10514,659 10430,743 10134,743 9859,468 6648.2,468 6465,284.8 6465,80 6426,41 6142,41 6076,107 6076,563 6306,793 9254,793 9714,1253 10430,1253 10514,1337 10514,2359 10343,2531 9150,2531 8333,3348 8300,3348 6646.31,3348 6465,3166.69 6465,2961.89 6426,2922.89 6142,2922.89 6076,2988.89 6076,3444.89 6306.11,3675 8606,3675 9239.02,3041
DC- on Pwr Layer "PWR_LAYER_DC-_P092" (solid, remove dead copper, pour order 92): 6601,1849.22 6601,2088.22 6638,2125.22 6914,2125.22 7284,1755.22 9267.79,1755.22 9568,1454.93 9568,1379 9507,1318 8656.22,1318 8547,1427.22 7023,1427.22
DC- on Pwr Layer "PWR_LAYER_DC-_P088" (solid, remove dead copper, pour order 88): 6601,7613 6601,7852 6638,7889 6914,7889 7284,7519 8963.08,7519 9568,6913.92 9568,6689 9534,6655 9306.46,6655 8770.45,7191 7023,7191
no net on M7 LPKF Text Top "TOP_LAYER_NONET_P-001" (solid, remove dead copper): 10689,6426 10785.45,6522.45 10785.45,6651 10690.45,6746 10556.45,6746 10465.45,6655 10465.45,6518.45 10557.9,6426
no net on M7 LPKF Text Top "TOP_LAYER_NONET_P-001" (solid, remove dead copper): 8766,258 8824,316 8824,398 8823.84,398 8763.84,458 8683,458 8683,457.84 8624.16,399 8624,399 8624,315 8681,258
no net on M7 LPKF Text Top "TOP_LAYER_NONET_P-001" (solid, remove dead copper): 312,7895 370,7953 370,8035 369.84,8035 309.84,8095 229,8095 229,8094.84 170.16,8036 170,8036 170,7952 227,7895
no net on M7 LPKF Text Top "TOP_LAYER_NONET_P-001" (solid, remove dead copper): 1623,6968 1623,7016 1660,7053 1708,7053 1743,7018 1743,6966 1710,6933 1658,6933
no net on M7 LPKF Text Top "TOP_LAYER_NONET_P-001" (solid, remove dead copper): 2582,7025 2640,7083 2640,7165 2639.84,7165 2579.84,7225 2499,7225 2499,7224.84 2440.16,7166 2440,7166 2440,7082 2497,7025
no net on M7 LPKF Text Top "TOP_LAYER_NONET_P-001" (solid, remove dead copper): 5064,5805 5064,5853 5101,5890 5149,5890 5184,5855 5184,5803 5151,5770 5099,5770
no net on M7 LPKF Text Top "TOP_LAYER_NONET_P-001" (solid, remove dead copper): 1120,4174 1216.45,4270.45 1216.45,4399 1121.45,4494 987.45,4494 896.45,4403 896.45,4266.45 988.9,4174
no net on M7 LPKF Text Top "TOP_LAYER_NONET_P-001" (solid, remove dead copper): 246,2253 342.45,2349.45 342.45,2478 247.45,2573 113.45,2573 22.45,2482 22.45,2345.45 114.9,2253

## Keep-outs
Keep-Out Layer:
  the board outline again, w10
  text ".Layer_Name" at -89.55,-1595.49 h60

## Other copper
Top Layer:
  text ".Layer_Name" at -89.55,-1595.49 h60
Gnd Layer:
  pour cut-out: 2898,6719.64 3035.16,6856.8 3232,6856.8 3369.77,6719.03 3369.77,6520.41 3232.76,6383.4 3035.55,6383.4 2898,6520.96
  pour cut-out: 2898,2839.84 3035.16,2977 3232,2977 3369.77,2839.23 3369.77,2640.61 3232.76,2503.6 3035.55,2503.6 2898,2641.16
  pour cut-out: 2898,3922.52 3035.16,4059.68 3232,4059.68 3369.77,3921.91 3369.77,3723.29 3232.76,3586.28 3035.55,3586.28 2898,3723.83
  pour cut-out: 2898,5636.97 3035.16,5774.12 3232,5774.12 3369.77,5636.35 3369.77,5437.74 3232.76,5300.73 3035.55,5300.73 2898,5438.28
  pour cut-out: 5508,1158 5609,1259 6953,1259 7055,1157 7055,1013 6953,911 5610,911 5508,1013
  pour cut-out: 5508,4039.89 5609,4140.89 6953,4140.89 7055,4038.89 7055,3894.89 6953,3792.89 5610,3792.89 5508,3894.89
  pour cut-out: 5508,6921.78 5609,7022.78 6953,7022.78 7055,6920.78 7055,6776.78 6953,6674.78 5610,6674.78 5508,6776.78
  pour cut-out: 6508,2118.63 6609,2219.63 6954,2219.63 7055,2118.63 7055,1974.63 6953,1872.63 6609,1872.63 6508,1973.63
  pour cut-out: 6508,5000.52 6609,5101.52 6954,5101.52 7055,5000.52 7055,4856.52 6953,4754.52 6609,4754.52 6508,4855.52
  pour cut-out: 5408,3079.26 5509,3180.26 6454,3180.26 6555,3079.26 6555,2935.26 6453,2833.26 5509,2833.26 5408,2934.26
  pour cut-out: 5408,5961.15 5509,6062.15 6454,6062.15 6555,5961.15 6555,5817.15 6453,5715.15 5509,5715.15 5408,5816.15
  pour cut-out: 7470,7191 7337,7058 7337,6698 7479,6556 8251,6556 8386,6691 8386,7052 8247,7191
  pour cut-out: 7385.16,6138.37 7337,6090.21 7337,5738.37 7479,5596.37 8442.37,5596.37 8578,5732 8578,5965 8311.63,6231.37 7478,6231.37 7444,6197.37
  pour cut-out: 7385.16,5177.74 7337,5129.58 7337,4777.74 7479,4635.74 8185.84,4635.74 8326.92,4776.82 8326.92,5150.82 8207,5270.74 7478,5270.74 7444,5236.74
  pour cut-out: 7385.16,4216.11 7337,4167.95 7337,3816.11 7479,3674.11 8185.84,3674.11 8326.92,3815.19 8326.92,4189.19 8207,4309.11 7478,4309.11 7444,4275.11
  pour cut-out: 7381.21,3260 7333.05,3211.84 7333.05,2860 7475.05,2718 8436.95,2718 8579.05,2860.11 8579.05,3101.52 8327.57,3353 7474.05,3353 7440.05,3319
  pour cut-out: 7385.16,2295.85 7337,2247.69 7337,1895.85 7479,1753.85 8185.84,1753.85 8326.92,1894.93 8326.92,2268.93 8207,2388.85 7478,2388.85 7444,2354.85
  pour cut-out: 7385.16,1334.22 7337,1286.06 7337,934.22 7479,792.22 8185.84,792.22 8326.92,933.3 8326.92,1307.3 8207,1427.22 7478,1427.22 7444,1393.22
  pour cut-out: 9391.94,5198.26 9536.94,5198.26 9637.94,5097.26 9637.94,4953.26 9535.94,4851.26 9391.94,4851.26 9290.94,4952.26 9290.94,5097.26
  pour cut-out: 9391.94,3410.26 9536.94,3410.26 9637.94,3309.26 9637.94,3165.26 9535.94,3063.26 9391.94,3063.26 9290.94,3164.26 9290.94,3309.26
  pour cut-out: 9391.94,1622.26 9536.94,1622.26 9637.94,1521.26 9637.94,1377.26 9535.94,1275.26 9391.94,1275.26 9290.94,1376.26 9290.94,1521.26
  text "'.Layer_Name'" at -89,-1594 h60
Pwr Layer:
  text "'.Layer_Name'" at -89,-1592 h60
Bottom Layer:
  text ".Layer_Name" at -89.55,-1595.49 h60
